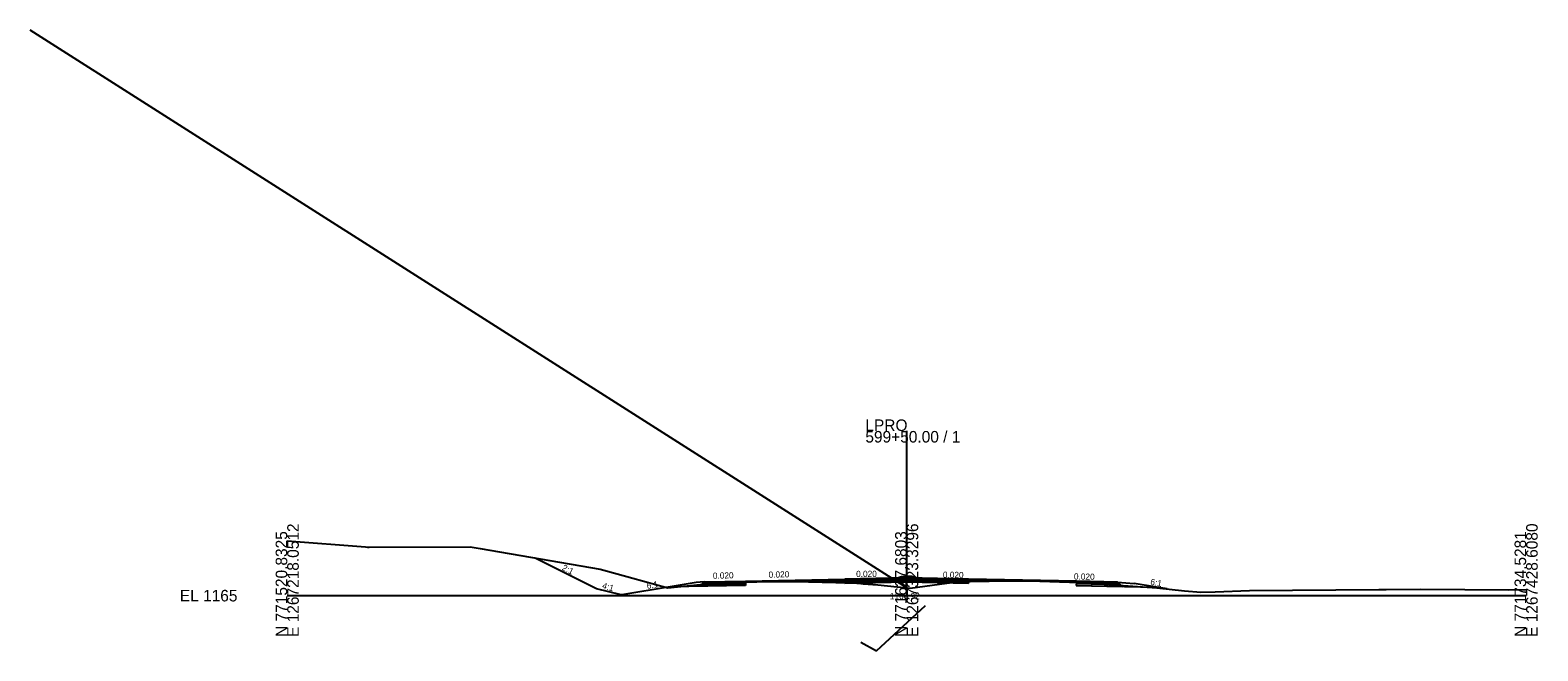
# Model space of a CAD drawing. Extents: x -3833 to 1267678, y -522 to 773248.
# Drawn here: x 937.8 to 1302.8, y 486.6 to 637 of the extents above; entities that cross this region are included whole.
import ezdxf

# ---------------------------------------------------------------- set-up
doc = ezdxf.new("R2010")
doc.units = 0
for name, color, linetype in [('Exist Cross Section Cell', 7, 'Continuous'), ('Exist XS Center Line Elevation Label', 7, 'Continuous'), ('Exist XS Ground Line', 7, 'Continuous'), ('Prop CMT DNC', 7, 'Continuous'), ('Prop CMT Pvmt Course 1', 7, 'Continuous'), ('Prop CMT Pvmt Course 2', 7, 'Continuous'), ('Prop CMT Pvmt Course 4', 7, 'Continuous'), ('Prop CMT Shld Paved Course 1', 7, 'Continuous'), ('Prop CMT Shld Paved Course 2', 7, 'Continuous'), ('Prop CMT Shld Paved Course 4', 7, 'Continuous'), ('Prop CMT Slope Grass', 7, 'Continuous'), ('Prop CMT Subgrade Earthwork', 7, 'Continuous'), ('Prop Conc Curb and Gutter', 7, 'Continuous'), ('Prop Corridor Mesh Bottom', 7, 'Continuous'), ('Prop XS Ditch Slope Text', 7, 'Continuous'), ('Prop XS Finish Grade', 7, 'Continuous'), ('Prop XS SE Text', 7, 'Continuous'), ('Scratch_Level_1', 7, 'Continuous'), ('Scratch_Level_5', 7, 'Continuous')]:
    doc.layers.add(name, color=color, linetype=linetype)

msp = doc.modelspace()

# ---------------------------------------------------------------- linework, layer by layer
at = {"layer": 'Exist Cross Section Cell'}
for p, q in [((1150, 500), (1150, 539.88)), ((1000, 500), (1150, 500)), ((1150, 500), (1300, 500))]:
    msp.add_line(p, q, dxfattribs=at)
at = {"layer": 'Exist XS Ground Line'}
for p, q in [((1000, 513.29), (1018.97, 511.79)), ((1018.97, 511.79), (1019.45, 511.75)), ((1019.45, 511.75), (1019.87, 511.75)), ((1019.87, 511.75), (1044.31, 511.86)), ((1044.31, 511.86), (1046.74, 511.38)), ((1046.74, 511.38), (1075.8, 506.41)), ((1075.8, 506.41), (1077.55, 505.92)), ((1077.55, 505.92), (1092.19, 501.92)), ((1092.19, 501.92), (1102.36, 502.9)), ((1102.36, 502.9), (1106.71, 503.23)), ((1106.71, 503.23), (1107.67, 503.28)), ((1107.67, 503.28), (1110.85, 503.34)), ((1110.85, 503.34), (1113.75, 503.35)), ((1113.75, 503.35), (1122.66, 503.41)), ((1122.66, 503.41), (1126.24, 503.32)), ((1126.24, 503.32), (1136.13, 503.09)), ((1136.13, 503.09), (1136.99, 503.06)), ((1136.99, 503.06), (1138.87, 502.96)), ((1138.87, 502.96), (1139.45, 502.87)), ((1139.45, 502.87), (1143.02, 502.59)), ((1143.02, 502.59), (1150, 501.92)), ((1150, 501.92), (1150.85, 501.83)), ((1150.85, 501.83), (1157.96, 502.78)), ((1157.96, 502.78), (1160.95, 503.15)), ((1160.95, 503.15), (1161.39, 503.19)), ((1161.39, 503.19), (1161.97, 503.26)), ((1161.97, 503.26), (1164.01, 503.35)), ((1164.01, 503.35), (1165.4, 503.42)), ((1165.4, 503.42), (1169.98, 503.48)), ((1169.98, 503.48), (1177.5, 503.58)), ((1177.5, 503.58), (1182.22, 503.47)), ((1182.22, 503.47), (1189.39, 503.29)), ((1189.39, 503.29), (1190.98, 503.19)), ((1190.98, 503.19), (1193.17, 503.06)), ((1193.17, 503.06), (1210.59, 501.9)), ((1210.59, 501.9), (1217.25, 501.18)), ((1217.25, 501.18), (1221.22, 500.81)), ((1221.22, 500.81), (1224.68, 500.88)), ((1224.68, 500.88), (1233.04, 501.21)), ((1233.04, 501.21), (1264.37, 501.51)), ((1264.37, 501.51), (1266.11, 501.52)), ((1266.11, 501.52), (1274.49, 501.53)), ((1274.49, 501.53), (1295.83, 501.42)), ((1295.83, 501.42), (1300, 501.46))]:
    msp.add_line(p, q, dxfattribs=at)
at = {"layer": 'Prop CMT Pvmt Course 1'}
for p, q in [((1111, 503.52), (1135, 504)), ((1135, 504), (1135, 504)), ((1135, 504), (1135, 504)), ((1135, 504), (1135, 503.75)), ((1147.75, 504.26), (1147, 504.24)), ((1147, 503.99), (1147.75, 504.01)), ((1152.25, 504.26), (1152.82, 504.25)), ((1152.82, 504), (1152.25, 504.01)), ((1152.82, 504.25), (1153, 504.24)), ((1153, 503.99), (1152.82, 504)), ((1191.09, 503.48), (1165, 504)), ((1165, 504), (1165, 504)), ((1165, 504), (1165, 503.75)), ((1135, 503.75), (1111, 503.34)), ((1111, 503.34), (1111, 503.52)), ((1111, 503.52), (1111, 503.52)), ((1135, 503.75), (1135, 503.75)), ((1165, 503.75), (1191.09, 503.42)), ((1191.09, 503.19), (1191.09, 503.48)), ((1191.09, 503.48), (1191.09, 503.48)), ((1191.09, 503.48), (1191.09, 503.48)), ((1191.09, 503.23), (1191.09, 503.23))]:
    msp.add_line(p, q, dxfattribs=at)
at = {"layer": 'Prop CMT Pvmt Course 2'}
for p, q in [((1150, 504.05), (1135, 503.75)), ((1147.75, 504.01), (1147, 503.99)), ((1165, 503.75), (1150, 504.05)), ((1150, 504.05), (1150, 504.05)), ((1150, 504.05), (1150, 504.05)), ((1152.25, 504.01), (1152.82, 504)), ((1152.82, 504), (1153, 503.99)), ((1135, 503.75), (1135, 503.75)), ((1135, 503.75), (1135, 503.42)), ((1135, 503.42), (1150, 503.72)), ((1135, 503.42), (1135, 503.42)), ((1150, 503.72), (1150, 503.72)), ((1150, 503.72), (1150, 503.72)), ((1150, 503.72), (1165, 503.42)), ((1165, 503.42), (1165, 503.75)), ((1165, 503.75), (1165, 503.75)), ((1165, 503.42), (1165, 503.42))]:
    msp.add_line(p, q, dxfattribs=at)
at = {"layer": 'Prop CMT Pvmt Course 4'}
for p, q in [((1147, 504.24), (1147, 503.21)), ((1148, 504.26), (1148, 503.23)), ((1152, 504.26), (1152, 503.23)), ((1153, 504.24), (1153, 503.21)), ((1135, 503.42), (1150, 503.72)), ((1135, 503.42), (1135, 503.42)), ((1135, 503.42), (1135, 503.42)), ((1150, 503.72), (1150, 503.72)), ((1150, 503.72), (1150, 503.72)), ((1150, 503.72), (1165, 503.42)), ((1165, 503.42), (1165, 503.42)), ((1165, 503.42), (1165, 503.42))]:
    msp.add_line(p, q, dxfattribs=at)
at = {"layer": 'Prop CMT Shld Paved Course 1'}
for p, q in [((1150, 504.3), (1135, 504)), ((1135, 503.75), (1150, 504.05)), ((1135, 504), (1135, 504)), ((1135, 504), (1135, 503.75)), ((1165, 504), (1150, 504.3)), ((1150, 504.3), (1150, 504.3)), ((1150, 504.3), (1150, 504.3)), ((1150, 504.05), (1150, 504.05)), ((1150, 504.05), (1150, 504.05)), ((1150, 504.05), (1165, 503.75)), ((1165, 503.75), (1165, 504)), ((1165, 504), (1165, 504)), ((1099.94, 502.26), (1101, 503.32)), ((1111, 503.27), (1100.74, 503.07)), ((1101, 503.32), (1111, 503.52)), ((1101, 503.32), (1101, 503.32)), ((1111, 503.52), (1111, 503.52)), ((1111, 503.52), (1111, 503.52)), ((1111, 503.52), (1111, 503.27)), ((1111, 503.27), (1111, 503.27)), ((1191.09, 503.48), (1191.09, 503.23)), ((1201.09, 503.28), (1191.09, 503.48)), ((1191.09, 503.23), (1201.34, 503.03)), ((1201.34, 503.03), (1201.09, 503.28))]:
    msp.add_line(p, q, dxfattribs=at)
at = {"layer": 'Prop CMT Shld Paved Course 2'}
for p, q in [((1111, 502.94), (1100.4, 502.73)), ((1100.74, 503.07), (1111, 503.27)), ((1100.74, 503.07), (1100.74, 503.07)), ((1111, 503.27), (1111, 503.27)), ((1111, 503.27), (1111, 503.27)), ((1111, 503.27), (1111, 502.94)), ((1111, 502.94), (1111, 502.94)), ((1115.52, 503.36), (1115.52, 503.36)), ((1122.66, 503.51), (1122.66, 503.51)), ((1122.66, 503.41), (1122.66, 503.41)), ((1126.24, 503.58), (1126.24, 503.58)), ((1126.24, 503.32), (1126.24, 503.32)), ((1135, 503.42), (1128.04, 503.28)), ((1128.04, 503.28), (1128.04, 503.28)), ((1135, 503.75), (1135, 503.75)), ((1135, 503.75), (1135, 503.75)), ((1135, 503.75), (1135, 503.12)), ((1135, 503.42), (1135, 503.42)), ((1165, 503.75), (1165, 503.75)), ((1165, 503.75), (1165, 503.75)), ((1165, 503.75), (1165, 503.4)), ((1165, 503.42), (1165, 503.42)), ((1165.32, 503.41), (1165.32, 503.41)), ((1169.98, 503.66), (1169.98, 503.66)), ((1169.98, 503.48), (1169.98, 503.48)), ((1175.13, 503.55), (1175.13, 503.55)), ((1175.13, 503.55), (1175.13, 503.55)), ((1190.98, 503.23), (1190.98, 503.23)), ((1190.98, 503.19), (1190.98, 503.19)), ((1201.34, 503.03), (1191.09, 503.23)), ((1191.09, 503.23), (1191.09, 503.23)), ((1191.09, 502.9), (1201.68, 502.69)), ((1201.68, 502.69), (1201.34, 503.03))]:
    msp.add_line(p, q, dxfattribs=at)
at = {"layer": 'Prop CMT Shld Paved Course 4'}
for p, q in [((1111, 502.48), (1099.94, 502.26)), ((1100.4, 502.73), (1100.9, 502.74)), ((1100.9, 502.74), (1111, 502.94)), ((1111, 502.94), (1111, 502.48)), ((1191.07, 502.44), (1202.15, 502.22)), ((1201.18, 502.7), (1191.09, 502.9)), ((1201.68, 502.69), (1201.18, 502.7)), ((1202.15, 502.22), (1201.68, 502.69))]:
    msp.add_line(p, q, dxfattribs=at)
at = {"layer": 'Prop CMT Slope Grass'}
for p, q in [((1099, 503.16), (1092.72, 502.12)), ((1101, 503.32), (1099, 503.16)), ((1201.09, 503.28), (1205.09, 502.96)), ((1210.53, 502.06), (1205.09, 502.96))]:
    msp.add_line(p, q, dxfattribs=at)
at = {"layer": 'Prop CMT Subgrade Earthwork'}
for p, q in [((1111, 502.48), (1092.72, 502.12)), ((1111, 503.34), (1111, 502.48)), ((1149.99, 503.27), (1135, 502.96)), ((1135, 502.96), (1135, 503.12)), ((1165, 502.96), (1149.99, 503.27)), ((1165, 502.96), (1165, 503.4)), ((1191.09, 503.19), (1191.07, 502.44)), ((1191.07, 502.44), (1210.53, 502.06))]:
    msp.add_line(p, q, dxfattribs=at)
at = {"layer": 'Prop Conc Curb and Gutter'}
for p, q in [((1147.99, 504.26), (1148, 504.42)), ((1147.99, 504.26), (1147.99, 504.13)), ((1147.99, 504.13), (1150, 504.13)), ((1148, 504.42), (1148.75, 504.67)), ((1148.75, 504.67), (1150, 504.7)), ((1151.24, 504.67), (1150, 504.7)), ((1152, 504.13), (1150, 504.13)), ((1151.99, 504.42), (1151.24, 504.67)), ((1152, 504.25), (1151.99, 504.42)), ((1152, 504.25), (1152, 504.13))]:
    msp.add_line(p, q, dxfattribs=at)
at = {"layer": 'Prop Corridor Mesh Bottom'}
for p, q in [((1135, 504), (1135, 503.75)), ((1165, 504), (1165, 503.75)), ((1111, 503.52), (1111, 503.27)), ((1191.09, 503.48), (1191.09, 503.23))]:
    msp.add_line(p, q, dxfattribs=at)
at = {"layer": 'Prop XS Finish Grade'}
for p, q in [((1074.9, 501.66), (1060.02, 509.11)), ((1080.9, 500.16), (1074.9, 501.66)), ((1092.72, 502.12), (1081, 500.16)), ((1201.09, 503.28), (1205.09, 502.96)), ((1213.11, 501.63), (1210.53, 502.06)), ((1080.95, 500.16), (1080.9, 500.16)), ((1081, 500.16), (1080.95, 500.16))]:
    msp.add_line(p, q, dxfattribs=at)
at = {"layer": 'Scratch_Level_1'}
msp.add_line((1150, 501.92), (937.75, 636.98), dxfattribs=at)
at = {"layer": 'Scratch_Level_5'}
for p, q in [((1142.71, 486.62), (1154.57, 497.65)), ((1138.93, 488.73), (1142.71, 486.62))]:
    msp.add_line(p, q, dxfattribs=at)

# ---------------------------------------------------------------- texts
at = {"layer": 'Exist Cross Section Cell'}
for s, p in [('LPRO', (1140, 539.88)), ('599+50.00 / 1', (1140, 537.08)), ('EL 1165', (974, 498.6))]:
    msp.add_text(s, height=2.8, dxfattribs=at).set_placement(p)
for s, p in [('N 771520.8325', (1000, 490)), ('E 1267218.0512', (1002.8, 490)), ('N 771627.6803', (1150, 490)), ('E 1267323.3296', (1152.8, 490)), ('N 771734.5281', (1300, 490)), ('E 1267428.6080', (1302.8, 490))]:
    msp.add_text(s, height=2.8, rotation=90, dxfattribs=at).set_placement(p)
at = {"layer": 'Exist XS Center Line Elevation Label'}
msp.add_text('1166.92', height=1.5, dxfattribs=at).set_placement((1145.92, 499.14))
at = {"layer": 'Prop CMT DNC'}
for p in [(1056.49, 509.71), (1135, 504), (1135, 504), (1150, 504.3), (1165, 504), (1165, 504), (1101, 503.32), (1111, 503.52), (1111, 503.52), (1191.09, 503.48), (1191.09, 503.48), (1201.09, 503.28), (1229.93, 501.09), (1080.95, 500.16), (1081, 500.16)]:
    msp.add_text('X', height=0.00025, dxfattribs=at).set_placement(p)
at = {"layer": 'Prop XS Ditch Slope Text'}
for s, rotation, p in [('2:1', 334.1731, (1066.4, 506.26)), ('6:1', 349.5777, (1208.91, 502.66)), ('4:1', 343.7547, (1076.16, 501.79)), ('6:1', 9.0286, (1087.17, 501.63))]:
    msp.add_text(s, height=1.5, rotation=rotation, dxfattribs=at).set_placement(p)
at = {"layer": 'Prop XS SE Text'}
for rotation, p in [(1.397, (1103.09, 504.07)), (1.397, (1116.58, 504.32)), (0.2693, (1137.76, 504.51)), (358.8542, (1158.75, 504.33)), (358.8542, (1190.49, 503.91))]:
    msp.add_text('0.020', height=1.5, rotation=rotation, dxfattribs=at).set_placement(p)

doc.saveas('drawing.dxf')
